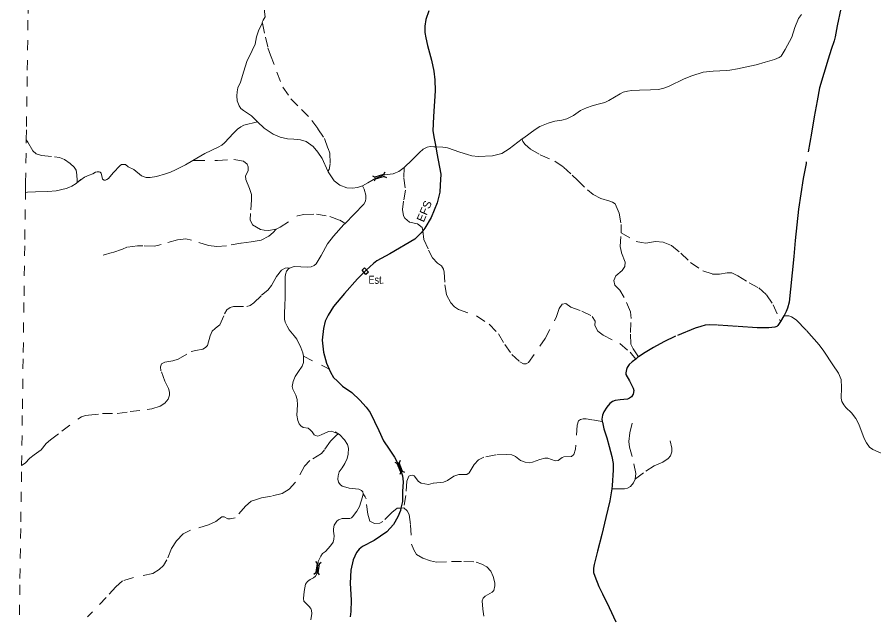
# Model space of a CAD drawing. Extents: x 703.1 to 728.9, y 7316.2 to 7344.3.
# Drawn here: x 703.12 to 711.69, y 7322.44 to 7328.43 of the extents above; entities that cross this region are included whole.
import ezdxf
from ezdxf.enums import TextEntityAlignment as Align

# ---------------------------------------------------------------- set-up
doc = ezdxf.new("R2010")
doc.units = 0
doc.header["$LTSCALE"] = 0.032
for name, pattern in [('DOTTED', [1.5, 0.3, -1.2]), ('LONG_DASHED', [7.5, 6, -1.5]), ('MEDIUM_DASHED', [4.5, 3, -1.5]), ('SHORT_DASHED', [2.7, 1.5, -1.2])]:
    doc.linetypes.add(name, pattern=pattern)
for name, color, linetype, lineweight in [('10', 7, 'Continuous', 25), ('15', 7, 'Continuous', 25), ('28', 7, 'Continuous', 25), ('4', 7, 'LONG_DASHED', 25), ('5', 7, 'LONG_DASHED', 13), ('58', 7, 'SHORT_DASHED', 13), ('6', 7, 'MEDIUM_DASHED', 13), ('7', 7, 'DOTTED', 13)]:
    doc.layers.add(name, color=color, linetype=linetype, lineweight=lineweight)
doc.layers.add('61', color=7, linetype='Continuous')

msp = doc.modelspace()

# ---------------------------------------------------------------- linework, layer by layer
at = {"layer": '10'}
for p, q in [((706.6772, 7326.8458), (706.6992, 7326.8339)), ((706.7879, 7326.8601), (706.6992, 7326.8339)), ((706.7998, 7326.8819), (706.7879, 7326.8601)), ((706.7936, 7326.8409), (706.8154, 7326.8288)), ((706.9531, 7323.998), (706.9433, 7323.9751)), ((706.9777, 7323.8892), (706.9433, 7323.9751)), ((706.9592, 7323.8817), (706.9492, 7323.8589)), ((707.0006, 7323.8795), (706.9777, 7323.8892)), ((706.1072, 7322.9887), (706.1223, 7322.969)), ((706.1223, 7322.969), (706.1096, 7322.8773)), ((706.1421, 7322.9662), (706.162, 7322.9811)), ((706.0897, 7322.8622), (706.1096, 7322.8773))]:
    msp.add_line(p, q, dxfattribs=at)
for points in [[(706.7936, 7326.8409), (706.7048, 7326.8148), (706.6928, 7326.7928)], [(706.9592, 7323.8817), (706.9248, 7323.9676), (706.9018, 7323.9775)], [(706.1421, 7322.9662), (706.1294, 7322.8746), (706.1445, 7322.8546)]]:
    msp.add_lwpolyline(points, dxfattribs=at)
at = {"layer": '15'}
for points in [[(707.2407, 7328.4962), (707.2099, 7328.4111), (707.1998, 7328.3431), (707.1998, 7328.2789), (707.2099, 7328.226), (707.2263, 7328.1517), (707.2659, 7328.0037), (707.2898, 7327.8941), (707.2999, 7327.8084), (707.3017, 7327.6982), (707.2879, 7327.4401), (707.2809, 7327.2958), (707.2935, 7327.2215), (707.3087, 7327.1368)], [(707.3087, 7327.1368), (707.32, 7327.0742), (707.3583, 7326.8632), (707.3546, 7326.7536), (707.3492, 7326.684), (707.3237, 7326.578), (707.2633, 7326.4281), (707.2009, 7326.3216), (707.1791, 7326.2952)], [(707.1791, 7326.2952), (707.1644, 7326.2775), (707.1015, 7326.2133), (706.8515, 7326.0654), (706.7206, 7325.9961), (706.6879, 7325.9684), (706.6136, 7325.9016), (706.528, 7325.8147), (706.3978, 7325.6705), (706.287, 7325.5408), (706.2335, 7325.452), (706.2045, 7325.3928), (706.1882, 7325.3185), (706.1743, 7325.2026), (706.1863, 7325.0824), (706.2153, 7324.9715), (706.2424, 7324.9121)], [(706.2424, 7324.9121), (706.2555, 7324.8834), (706.2877, 7324.8298), (706.3254, 7324.7933), (706.377, 7324.7417), (706.4702, 7324.6799), (706.5508, 7324.6031), (706.6143, 7324.532), (706.6546, 7324.4804), (706.739, 7324.3002), (706.7874, 7324.1963), (706.8441, 7324.1107), (706.8963, 7324.032), (706.9479, 7323.9401), (706.9781, 7323.8444), (706.9832, 7323.7839), (706.9775, 7323.6876), (706.975, 7323.5881), (706.9615, 7323.5232)], [(706.9615, 7323.5232), (706.9561, 7323.4974), (706.9302, 7323.4338), (706.8874, 7323.357), (706.8207, 7323.2852), (706.6936, 7323.1996), (706.5758, 7323.1385), (706.5419, 7323.112), (706.5179, 7323.078), (706.4827, 7323.005), (706.46, 7322.9004), (706.4519, 7322.7701), (706.4619, 7322.6013), (706.4601, 7322.4886), (706.4525, 7322.4332)]]:
    msp.add_lwpolyline(points, dxfattribs=at)
at = {"layer": '28'}
msp.add_lwpolyline([(706.6111, 7325.8601), (706.572, 7325.9016), (706.5967, 7325.9249), (706.6358, 7325.8834)], close=True, dxfattribs=at)
at = {"layer": '4'}
for points in [[(711.3581, 7328.5199), (711.3217, 7328.3467), (711.301, 7328.2363), (711.2934, 7328.197), (711.2627, 7328.1108), (711.231, 7328.015), (711.1875, 7327.8703), (711.1466, 7327.7262), (711.1235, 7327.5968), (711.0933, 7327.4357), (711.067, 7327.2745), (711.0106, 7326.9712), (710.983, 7326.8195), (710.9598, 7326.6679), (710.9372, 7326.5131), (710.9204, 7326.3571), (710.9011, 7326.1991), (710.8881, 7326.0398), (710.872, 7325.8773), (710.857, 7325.7124), (710.8409, 7325.581), (710.8259, 7325.5227), (710.8114, 7325.489), (710.7917, 7325.4503), (710.7884, 7325.4448), (710.7549, 7325.3893)], [(710.7549, 7325.3893), (710.7298, 7325.3476), (710.7203, 7325.338), (710.6975, 7325.3317), (710.6397, 7325.3254), (710.5224, 7325.3266), (710.3241, 7325.34), (710.1259, 7325.3533), (710.0483, 7325.3558), (710.0019, 7325.3513), (709.9601, 7325.3393), (709.903, 7325.3209), (709.706, 7325.2415)], [(709.706, 7325.2415), (709.5887, 7325.1857), (709.4854, 7325.1286), (709.4029, 7325.0798), (709.3368, 7325.0343)], [(709.308, 7325.0133), (709.2713, 7324.9858), (709.2428, 7324.9586), (709.2238, 7324.9306), (709.2155, 7324.9084), (709.2095, 7324.8767), (709.2102, 7324.8602), (709.245, 7324.7942), (709.2828, 7324.7232), (709.2904, 7324.7003), (709.2822, 7324.6635), (709.265, 7324.6344), (709.2476, 7324.6236), (709.2248, 7324.6134), (709.1512, 7324.6058), (709.1011, 7324.5995), (709.0751, 7324.5881), (709.0504, 7324.5697), (709.0193, 7324.5329), (708.9901, 7324.484), (708.9771, 7324.4511), (708.9708, 7324.4136), (708.9738, 7324.3886)], [(709.3368, 7325.0343), (709.3272, 7325.0277), (709.308, 7325.0133)], [(708.9738, 7324.3886), (708.9746, 7324.3819), (708.9892, 7324.3165), (709.0199, 7324.2245), (709.0434, 7324.1395), (709.069, 7324.0393), (709.0821, 7323.9689), (709.0827, 7323.9023), (709.0735, 7323.7482), (709.0682, 7323.7167)], [(709.0682, 7323.7167), (709.0478, 7323.5946), (709.0106, 7323.4271), (708.9691, 7323.2596), (708.9251, 7323.0909), (708.8924, 7322.9576), (708.8876, 7322.9202), (708.8876, 7322.8796), (708.9003, 7322.8409), (708.9393, 7322.7382), (708.9767, 7322.6652), (709.0442, 7322.5275), (709.1086, 7322.386)]]:
    msp.add_lwpolyline(points, dxfattribs=at)
at = {"layer": '5'}
for points in [[(710.9667, 7328.4594), (710.9365, 7328.4204), (710.8998, 7328.3314), (710.8693, 7328.2342), (710.8024, 7328.1114), (710.7638, 7328.0451), (710.741, 7328.0312), (710.6962, 7328.0098), (710.6035, 7327.9834), (710.5131, 7327.9576), (710.3252, 7327.9179), (710.2488, 7327.9032), (710.2146, 7327.9003), (710.0808, 7327.8944), (709.983, 7327.8841), (709.8701, 7327.8459), (709.7922, 7327.8165), (709.6418, 7327.7444), (709.5896, 7327.7223), (709.5345, 7327.7105), (709.4562, 7327.7061), (709.3452, 7327.7047), (709.2709, 7327.6995), (709.2264, 7327.6922), (709.1838, 7327.6826), (709.1529, 7327.6679), (709.0389, 7327.5995), (709.0007, 7327.5811), (708.932, 7327.562), (708.8717, 7327.5466), (708.8173, 7327.5274), (708.7548, 7327.4995), (708.6864, 7327.4509), (708.6206, 7327.4178), (708.5699, 7327.4046), (708.4985, 7327.3928), (708.4324, 7327.373), (708.3512, 7327.3413), (708.3034, 7327.3112), (708.1894, 7327.2266), (708.1744, 7327.2153)], [(705.527, 7327.3862), (705.5011, 7327.4136), (705.4678, 7327.4454), (705.3871, 7327.4995), (705.359, 7327.5217), (705.3434, 7327.5476), (705.3227, 7327.5972), (705.3197, 7327.6454), (705.3234, 7327.6876), (705.3312, 7327.7261), (705.3578, 7327.7846), (705.3897, 7327.8949), (705.4197, 7327.9912), (705.473, 7328.1008), (705.5052, 7328.1653), (705.5156, 7328.2364), (705.5407, 7328.306), (705.5692, 7328.3623), (705.5753, 7328.3722)], [(705.527, 7327.3862), (705.3917, 7327.352), (705.3612, 7327.3364), (705.3274, 7327.3134), (705.2854, 7327.2749), (705.1971, 7327.1763), (705.1701, 7327.1528), (705.1335, 7327.1321), (705.0015, 7327.0687), (704.8797, 7326.999)], [(706.2294, 7326.8941), (706.172, 7327.0194), (706.1295, 7327.0843), (706.0835, 7327.1388), (706.0138, 7327.189), (705.956, 7327.2059), (705.8907, 7327.212), (705.828, 7327.2163), (705.7552, 7327.2327), (705.6852, 7327.2628), (705.5939, 7327.3224), (705.527, 7327.3862)], [(708.1744, 7327.2153), (708.042, 7327.1155), (707.9707, 7327.0684), (707.8748, 7327.0463), (707.7328, 7327.0404), (707.6699, 7327.0462), (707.6251, 7327.0595), (707.5508, 7327.0845), (707.4276, 7327.1279), (707.3802, 7327.1345), (707.3087, 7327.1368)], [(707.3087, 7327.1368), (707.2905, 7327.1374), (707.2544, 7327.1389), (707.2243, 7327.133), (707.1817, 7327.1117), (707.1471, 7327.0793), (707.0725, 7327.0079), (706.992, 7326.9291)], [(704.8797, 7326.999), (704.8078, 7326.9578), (704.7075, 7326.9061), (704.6573, 7326.8817), (704.6066, 7326.8666), (704.5162, 7326.8413), (704.4551, 7326.83), (704.4143, 7326.8314), (704.3657, 7326.8451), (704.2906, 7326.9108), (704.2335, 7326.9381), (704.2058, 7326.9583), (704.1908, 7326.9597), (704.1824, 7326.9597), (704.1683, 7326.9588), (704.1528, 7326.9498), (704.0847, 7326.8752), (704.0375, 7326.8207), (704.0197, 7326.8084), (704.0084, 7326.8023), (703.9938, 7326.8042), (703.9783, 7326.8131), (703.9727, 7326.8305), (703.9647, 7326.8747), (703.9525, 7326.8817), (703.9426, 7326.8864), (703.9243, 7326.8869), (703.9079, 7326.8827), (703.8792, 7326.8681), (703.8442, 7326.8522), (703.7987, 7326.8334), (703.7256, 7326.779)], [(706.992, 7326.9291), (706.9655, 7326.9085), (706.9391, 7326.8909), (706.9067, 7326.8776), (706.8839, 7326.8673), (706.7971, 7326.8563), (706.71, 7326.824), (706.6298, 7326.7769), (706.5772, 7326.7468)], [(706.5772, 7326.7468), (706.5273, 7326.7296), (706.4761, 7326.7225), (706.4216, 7326.7281), (706.3484, 7326.7535), (706.292, 7326.7981), (706.2333, 7326.8855), (706.2294, 7326.8941)], [(703.7256, 7326.779), (703.7602, 7326.8094), (703.7137, 7326.7686), (703.6698, 7326.7427), (703.6421, 7326.7282), (703.6137, 7326.7183), (703.5132, 7326.6957), (703.4294, 7326.6901), (703.3068, 7326.6864), (703.2275, 7326.6822), (703.2074, 7326.6812)], [(706.5772, 7326.7468), (706.5919, 7326.7137), (706.6089, 7326.6519), (706.6089, 7326.6181), (706.6074, 7326.593), (706.589, 7326.5614), (706.4945, 7326.4636), (706.4023, 7326.3711)], [(706.4023, 7326.3711), (706.3912, 7326.3599), (706.2864, 7326.2415), (706.2257, 7326.1658), (706.1632, 7326.0503), (706.115, 7325.9657), (706.0937, 7325.9502), (706.0628, 7325.9377), (706.0261, 7325.9318), (705.8945, 7325.9384), (705.8621, 7325.9303), (705.8514, 7325.924)], [(705.8514, 7325.924), (705.8408, 7325.9178), (705.8184, 7325.8921), (705.8059, 7325.8597), (705.8022, 7325.8369), (705.8022, 7325.7567), (705.8048, 7325.6324), (705.7989, 7325.5456), (705.7971, 7325.4772), (705.7978, 7325.4331), (705.7985, 7325.4118), (705.8051, 7325.3809), (705.8221, 7325.3411), (705.8438, 7325.3044), (705.8938, 7325.2463), (705.9192, 7325.2117), (705.9607, 7325.1307), (705.9791, 7325.0748), (705.9862, 7325.0413)], [(711.7913, 7324.057), (711.6784, 7324.1075), (711.6444, 7324.1332), (711.6159, 7324.1755), (711.593, 7324.2177), (711.5384, 7324.3619), (711.509, 7324.4179), (711.4668, 7324.4739), (711.4103, 7324.529), (711.3901, 7324.5566), (711.3699, 7324.5878), (711.3617, 7324.6227), (711.3663, 7324.7292), (711.3631, 7324.8082), (711.3365, 7324.8716), (711.2786, 7324.957), (711.1882, 7325.0938), (711.1432, 7325.1545), (711.0133, 7325.3033), (710.9119, 7325.4071), (710.8669, 7325.4355), (710.8393, 7325.4447), (710.8084, 7325.4448), (710.7884, 7325.4448)], [(705.9862, 7325.0413), (705.9872, 7325.0366), (705.9861, 7324.9784), (705.9729, 7324.9417), (705.9361, 7324.8887), (705.9023, 7324.8387), (705.8821, 7324.7879), (705.8725, 7324.7386), (705.8806, 7324.7114), (705.9093, 7324.6533), (705.9229, 7324.6098), (705.9273, 7324.5539), (705.9214, 7324.4517), (705.9291, 7324.3987), (705.9446, 7324.3648), (705.9585, 7324.345), (705.9843, 7324.3303), (706.0321, 7324.3207), (706.0548, 7324.306), (706.074, 7324.2847), (706.0931, 7324.2567), (706.1056, 7324.2471), (706.1298, 7324.2405), (706.1637, 7324.2538), (706.2369, 7324.2898), (706.2677, 7324.2927), (706.3339, 7324.2668)], [(706.3339, 7324.2668), (706.3038, 7324.2854), (706.3457, 7324.2596), (706.3964, 7324.2067), (706.4258, 7324.1589), (706.4379, 7324.1221), (706.435, 7324.0625), (706.424, 7324.0198), (706.4004, 7323.9698), (706.3721, 7323.9263), (706.3427, 7323.8837), (706.3324, 7323.8462), (706.3317, 7323.8123), (706.3383, 7323.7822), (706.3526, 7323.7579), (706.374, 7323.7402), (706.41, 7323.7307), (706.4445, 7323.7226), (706.5387, 7323.7115), (706.5673, 7323.6976), (706.5798, 7323.685), (706.5835, 7323.6659)], [(706.5835, 7323.6659), (706.5754, 7323.6336), (706.5471, 7323.5387), (706.5214, 7323.4923), (706.478, 7323.4335), (706.4659, 7323.4239), (706.4497, 7323.4195), (706.3732, 7323.4187), (706.3379, 7323.4048), (706.3196, 7323.393), (706.2931, 7323.3503), (706.2865, 7323.3135), (706.2872, 7323.2929), (706.2938, 7323.2437), (706.2912, 7323.2105), (706.2824, 7323.1819)], [(706.2824, 7323.1819), (706.2567, 7323.1443), (706.2059, 7323.0899), (706.1783, 7323.0686), (706.1585, 7323.0414), (706.1423, 7323.0098), (706.1342, 7322.9884)], [(706.1342, 7322.9884), (706.1185, 7322.8663), (706.1082, 7322.8399), (706.0868, 7322.8244), (706.0523, 7322.8068), (706.028, 7322.7869), (706.0082, 7322.7612), (705.9927, 7322.6891), (705.9872, 7322.6177), (705.9901, 7322.5919), (706.0416, 7322.5405), (706.06, 7322.5184), (706.0659, 7322.4985), (706.0685, 7322.4684), (706.0604, 7322.4044)]]:
    msp.add_lwpolyline(points, dxfattribs=at)
at = {"layer": '58'}
for points in [[(703.215, 7327.2082), (703.2169, 7327.34), (703.225, 7327.9052), (703.233, 7328.4703), (703.2411, 7329.0354), (703.2492, 7329.6005), (703.2522, 7329.8091), (703.2555, 7330.04)], [(703.2074, 7326.6812), (703.2088, 7326.7749), (703.215, 7327.2082)], [(703.1684, 7323.9498), (703.1765, 7324.5144), (703.1846, 7325.0796), (703.1927, 7325.6447), (703.2007, 7326.2098), (703.2074, 7326.6812)], [(703.1239, 7320.8393), (703.128, 7321.1237), (703.1361, 7321.6888), (703.1442, 7322.254), (703.1522, 7322.8191), (703.1603, 7323.3842), (703.1684, 7323.9493), (703.1684, 7323.9498)]]:
    msp.add_lwpolyline(points, dxfattribs=at)
at = {"layer": '6'}
for p, q in [((705.9862, 7325.0413), (706.2053, 7324.9329)), ((706.2053, 7324.9329), (706.2424, 7324.9121)), ((706.9894, 7323.5251), (706.9615, 7323.5232))]:
    msp.add_line(p, q, dxfattribs=at)
for points in [[(705.6035, 7328.5449), (705.5981, 7328.5409), (705.5932, 7328.5312), (705.5969, 7328.4863), (705.6042, 7328.4365), (705.5823, 7328.4038), (705.5726, 7328.3844), (705.5753, 7328.3722), (705.6054, 7328.2339)], [(705.6054, 7328.2339), (705.6314, 7328.1266), (705.6581, 7328.0538), (705.7212, 7327.8851), (705.78, 7327.7341), (705.8612, 7327.6176), (705.9661, 7327.5115), (706.0717, 7327.4011), (706.1317, 7327.3167), (706.1972, 7327.2185), (706.2323, 7327.1214), (706.2487, 7327.0722), (706.2548, 7326.9679), (706.2439, 7326.9096), (706.2294, 7326.8941)], [(708.1744, 7327.2153), (708.1804, 7327.1898), (708.2041, 7327.1603), (708.2573, 7327.1145), (708.3539, 7327.0571), (708.4995, 7326.9925), (708.585, 7326.9331), (708.6717, 7326.8545), (708.7252, 7326.8034), (708.8275, 7326.706), (708.882, 7326.6605), (708.9589, 7326.6196), (709.0481, 7326.5934), (709.0771, 7326.5839), (709.1025, 7326.5651), (709.1434, 7326.4734), (709.1626, 7326.3584), (709.1618, 7326.2748)], [(704.8797, 7326.999), (704.8998, 7326.999), (705.1269, 7326.9991), (705.2903, 7327.0088), (705.3878, 7326.9918), (705.4227, 7326.9625), (705.4325, 7326.9349), (705.4333, 7326.8967), (705.4073, 7326.8454), (705.4105, 7326.8097), (705.4483, 7326.719), (705.4662, 7326.6613), (705.4654, 7326.6076), (705.4561, 7326.4682), (705.4549, 7326.4061), (705.4784, 7326.3573), (705.5565, 7326.311), (705.5922, 7326.3045), (705.6361, 7326.2996), (705.712, 7326.3146)], [(706.992, 7326.9291), (706.9914, 7326.8248), (707.0056, 7326.7035), (706.9882, 7326.5947), (706.9772, 7326.5112), (706.9882, 7326.4466), (707.0008, 7326.423), (707.0465, 7326.382), (707.1253, 7326.3647), (707.1741, 7326.33), (707.1791, 7326.2952)], [(705.712, 7326.3146), (705.7528, 7326.3334), (705.9279, 7326.4458), (705.9889, 7326.4608), (706.1163, 7326.4643), (706.2516, 7326.4396), (706.3489, 7326.4033), (706.3823, 7326.3832), (706.4023, 7326.3711)], [(705.712, 7326.3146), (705.6852, 7326.2788), (705.6389, 7326.2414), (705.5625, 7326.2032), (705.4642, 7326.1878), (705.3618, 7326.174), (705.2159, 7326.1459), (705.1201, 7326.1402), (705.0364, 7326.1483), (704.8678, 7326.204), (704.8101, 7326.2162), (704.728, 7326.2073), (704.5634, 7326.1597), (704.5269, 7326.1483), (704.4944, 7326.1434), (704.3814, 7326.1475), (704.3274, 7326.1471), (704.2209, 7326.1317), (704.177, 7326.1122), (704.0746, 7326.078), (703.9848, 7326.0516)], [(707.1791, 7326.2952), (707.1914, 7326.2086), (707.2379, 7326.1038), (707.2757, 7326.025), (707.3261, 7325.9714), (707.367, 7325.9446), (707.3875, 7325.9131), (707.3922, 7325.8816), (707.4001, 7325.7571), (707.4166, 7325.6555), (707.4607, 7325.5767), (707.497, 7325.5357), (707.5348, 7325.5089), (707.7175, 7325.4459), (707.8427, 7325.3632), (707.9356, 7325.2655), (707.9986, 7325.1599), (708.0687, 7325.0583), (708.149, 7324.9858), (708.1852, 7324.9653), (708.2136, 7324.9653), (708.2372, 7324.9779), (708.4042, 7325.219), (708.5176, 7325.438), (708.5428, 7325.52), (708.5743, 7325.561), (708.6105, 7325.5704), (708.6593, 7325.531), (708.7703, 7325.494), (708.8743, 7325.4404), (708.9026, 7325.3915), (708.8979, 7325.3506), (708.931, 7325.2938), (708.983, 7325.2513), (709.1499, 7325.1678), (709.2515, 7325.0834), (709.308, 7325.0133)], [(709.3368, 7325.0343), (709.283, 7325.1165), (709.2578, 7325.1638), (709.2547, 7325.2788), (709.261, 7325.4191), (709.2547, 7325.4869), (709.1941, 7325.6295), (709.15, 7325.7036), (709.098, 7325.7524), (709.0885, 7325.7997), (709.1106, 7325.8454), (709.1736, 7325.899), (709.1996, 7325.9408), (709.2043, 7325.9833), (709.1649, 7326.081), (709.1539, 7326.1409), (709.1618, 7326.2748)], [(709.1618, 7326.2748), (709.3138, 7326.1905), (709.3673, 7326.1795), (709.4099, 7326.1732), (709.5059, 7326.1905), (709.5831, 7326.1842), (709.665, 7326.1511), (709.7595, 7326.0723), (709.8548, 7325.9801), (709.9776, 7325.8966), (710.0753, 7325.8635), (710.1446, 7325.8619), (710.2218, 7325.8777), (710.2706, 7325.8777), (710.3304, 7325.8446), (710.4423, 7325.7768), (710.5376, 7325.7256), (710.6163, 7325.6562), (710.6809, 7325.557), (710.7461, 7325.4093), (710.7549, 7325.3893)], [(708.9738, 7324.3886), (708.8678, 7324.4065), (708.8128, 7324.4155), (708.7812, 7324.4155), (708.7551, 7324.4092), (708.737, 7324.3947), (708.7226, 7324.3505), (708.7055, 7324.1114), (708.6911, 7324.0582), (708.6658, 7324.0384), (708.5901, 7324.0366), (708.5725, 7324.028), (708.5337, 7323.9974), (708.503, 7323.9965), (708.4309, 7324.0208), (708.4011, 7324.0217), (708.3497, 7324.0073), (708.2749, 7323.9811), (708.2455, 7323.9761), (708.2014, 7323.9816), (708.1572, 7323.9996), (708.1076, 7324.0384), (708.0688, 7324.0564), (708.0183, 7324.0591), (707.9083, 7324.0546), (707.7888, 7324.0316), (707.7356, 7324.0054), (707.6923, 7323.9585), (707.6418, 7323.8746), (707.6183, 7323.8593), (707.5723, 7323.8584), (707.5408, 7323.8584), (707.4907, 7323.8426), (707.4276, 7323.7993), (707.3852, 7323.7813), (707.2842, 7323.7704), (707.2355, 7323.7578), (707.1647, 7323.7727), (707.1368, 7323.7871), (707.0935, 7323.8466), (707.0736, 7323.8529), (707.0529, 7323.8475), (707.0403, 7323.8421), (707.0213, 7323.7916), (707.0105, 7323.6491), (706.9894, 7323.5251)], [(706.3339, 7324.2668), (706.3139, 7324.2475), (706.2575, 7324.1932), (706.1978, 7324.105), (706.1667, 7324.0684), (706.0514, 7323.9979), (705.9972, 7323.9436), (705.9077, 7323.7822), (705.844, 7323.713), (705.7749, 7323.6696), (705.6664, 7323.6411), (705.5674, 7323.6249), (705.5166, 7323.6093), (705.4651, 7323.5903), (705.4054, 7323.5415), (705.3051, 7323.4262), (705.255, 7323.414), (705.2306, 7323.414), (705.1926, 7323.4343), (705.1696, 7323.4343), (705.1099, 7323.3868), (705.0367, 7323.3543), (704.8557, 7323.3007), (704.7852, 7323.2655), (704.716, 7323.1936), (704.6659, 7323.1176), (704.6211, 7323.005), (704.5866, 7322.9474), (704.5446, 7322.9067), (704.4808, 7322.8687), (704.287, 7322.828), (704.1772, 7322.7954), (704.1107, 7322.7344), (704.0152, 7322.6293), (703.8579, 7322.4651), (703.8261, 7322.4359)], [(706.9615, 7323.5232), (706.9235, 7323.5205), (706.8712, 7323.479), (706.7811, 7323.3897), (706.749, 7323.3712), (706.6976, 7323.3667), (706.6489, 7323.392), (706.6291, 7323.4605), (706.612, 7323.6139), (706.6034, 7323.6342), (706.5835, 7323.6659)], [(706.9894, 7323.5251), (707.0242, 7323.4958), (707.044, 7323.457), (707.0566, 7323.3514), (707.067, 7323.1606), (707.09, 7323.1051), (707.118, 7323.0591), (707.1784, 7323.0203), (707.256, 7322.9951), (707.3173, 7322.9806), (707.4679, 7322.9878), (707.5909, 7322.9892), (707.7118, 7322.9828), (707.7686, 7322.9612), (707.82, 7322.9332), (707.8601, 7322.8903), (707.8826, 7322.8389), (707.8989, 7322.774), (707.8998, 7322.7442), (707.8885, 7322.6986), (707.874, 7322.6806), (707.8019, 7322.6418), (707.7821, 7322.622), (707.7731, 7322.5949), (707.7803, 7322.5128), (707.7888, 7322.4411)]]:
    msp.add_lwpolyline(points, dxfattribs=at)
at = {"layer": '7'}
for points in [[(703.215, 7327.2082), (703.2323, 7327.1843), (703.2804, 7327.0982), (703.3132, 7327.0674), (703.3665, 7327.05), (703.4977, 7327.0357), (703.5469, 7327.0305), (703.5971, 7327.009), (703.6534, 7326.9701), (703.6954, 7326.9332), (703.7139, 7326.9045), (703.7221, 7326.8563), (703.7247, 7326.7991), (703.7256, 7326.779)], [(704.5574, 7324.9343), (704.5688, 7324.9663), (704.6008, 7324.9834), (704.6821, 7324.9958), (704.734, 7325.0129), (704.8647, 7325.0875), (704.9106, 7325.0992), (704.9795, 7325.1134), (705.0065, 7325.1284), (705.0285, 7325.1483), (705.0548, 7325.2457), (705.0751, 7325.2937), (705.1042, 7325.3186), (705.1248, 7325.3356), (705.1494, 7325.3551), (705.1984, 7325.4653), (705.2193, 7325.5055), (705.2534, 7325.5296), (705.2875, 7325.5382), (705.419, 7325.5396), (705.4545, 7325.5481), (705.4919, 7325.5755), (705.5672, 7325.6515), (705.629, 7325.7034), (705.6685, 7325.7507), (705.7182, 7325.8402), (705.7683, 7325.9031), (705.8025, 7325.9223), (705.8259, 7325.9273), (705.8514, 7325.924)], [(703.1684, 7323.9498), (703.2035, 7323.9735), (703.2525, 7324.0233), (703.2951, 7324.056), (703.3655, 7324.1043), (703.4138, 7324.1676), (703.4564, 7324.2053), (703.5723, 7324.2934), (703.7296, 7324.4111), (703.7659, 7324.4345), (703.8064, 7324.4487), (703.838, 7324.4533), (703.9758, 7324.4675), (704.124, 7324.4679), (704.2526, 7324.4885), (704.425, 7324.508), (704.4697, 7324.5166), (704.5536, 7324.5422), (704.6015, 7324.5731), (704.6349, 7324.6115), (704.647, 7324.6506), (704.6456, 7324.6812), (704.6356, 7324.7196), (704.6012, 7324.7925), (704.5617, 7324.8966), (704.5574, 7324.9343)], [(709.3034, 7323.8133), (709.3089, 7323.867), (709.2728, 7324.0389), (709.2454, 7324.1331), (709.2377, 7324.1901), (709.2487, 7324.2766), (709.2788, 7324.3944)], [(709.6515, 7324.1956), (709.6701, 7324.1233), (709.6679, 7324.0838), (709.6548, 7324.0455), (709.634, 7324.017), (709.5793, 7323.982), (709.4928, 7323.9458), (709.3855, 7323.8746), (709.3034, 7323.8133)], [(709.3034, 7323.8133), (709.2874, 7323.775), (709.2569, 7323.7373), (709.2265, 7323.7205), (709.1951, 7323.7136), (709.1341, 7323.7136), (709.0682, 7323.7167)]]:
    msp.add_lwpolyline(points, dxfattribs=at)

# ---------------------------------------------------------------- texts
at = {"layer": '61', "width": 1.05}
msp.add_text('EFS', height=0.08, rotation=67.105, dxfattribs=at).set_placement((707.2309, 7326.4775), align=Align.CENTER)
at = {"layer": '61', "width": 0.85}
msp.add_text('Est.', height=0.08, dxfattribs=at).set_placement((706.6363, 7325.7662))

doc.saveas('drawing.dxf')
